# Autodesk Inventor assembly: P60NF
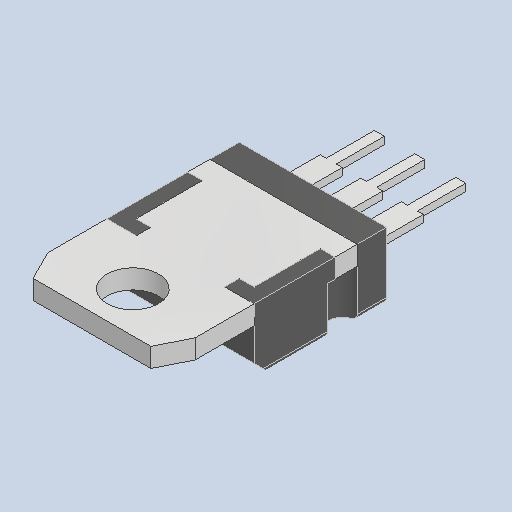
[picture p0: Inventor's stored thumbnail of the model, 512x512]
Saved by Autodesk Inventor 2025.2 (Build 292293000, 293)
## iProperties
Created: 2025-04
Part Number: P60NF
Description: PART--DESC
Document SubType Name: Assembly
Designer: BennF
Author: BennF
Revision Number: NONE
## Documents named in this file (4)
- C:\Users\BennF\Nextcloud\Benutzer\CNC JarBeRi\existing parts\Electronics\RepRap A4988 Shied (USE WITHOUT ARDUINO)\reprap-a4988-1.snapshot.1\RepRap\RepRap\P60NF.iam
- C:\Users\BennF\Nextcloud\Benutzer\CNC JarBeRi\existing parts\Electronics\RepRap A4988 Shied (USE WITHOUT ARDUINO)\reprap-a4988-1.snapshot.1\RepRap\RepRap\P60NF Geometry.ipt
- C:\Users\BennF\Nextcloud\Benutzer\CNC JarBeRi\existing parts\Electronics\RepRap A4988 Shied (USE WITHOUT ARDUINO)\reprap-a4988-1.snapshot.1\RepRap\RepRap\body.ipt
- C:\Users\BennF\Nextcloud\Benutzer\CNC JarBeRi\existing parts\Electronics\RepRap A4988 Shied (USE WITHOUT ARDUINO)\reprap-a4988-1.snapshot.1\RepRap\RepRap\Name.ipt
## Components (3 placed, 3 different names)
1. P60NF Geometry
2. body
3. Name
